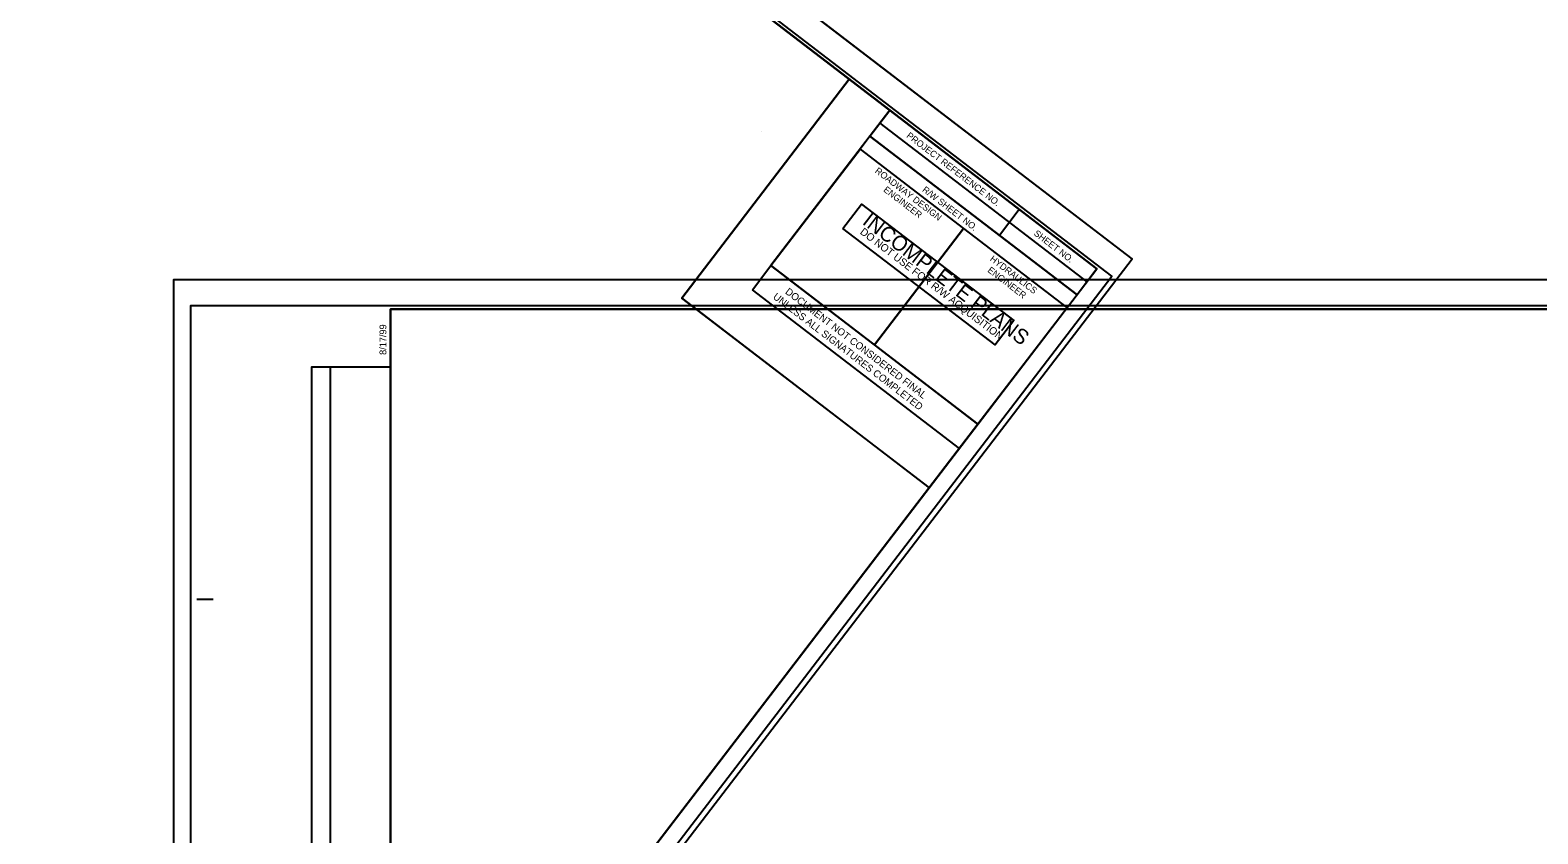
# Model space of a CAD drawing. Extents: x 1617779 to 1622406, y 896496 to 899510.
# Drawn here: x 1618935 to 1620092, y 898046 to 898662 of the extents above; entities that cross this region are included whole.
import ezdxf

# ---------------------------------------------------------------- set-up
doc = ezdxf.new("R2010")
doc.units = 0
for name, color, linetype in [('ControlPoints', 7, 'Continuous'), ('Exist Profile Cell', 7, 'Continuous'), ('Exist Vertical Profile Ground Line', 7, 'Continuous'), ('Exist Vertical Profile Horizontal Axis Label Major', 7, 'Continuous'), ('Observations', 7, 'Continuous'), ('Prop Horizontal Alignment', 7, 'Continuous'), ('Prop Horizontal Alignment Curve and Spiral Data', 7, 'Continuous'), ('Scratch_Level_4', 7, 'Continuous'), ('Setups', 7, 'Continuous')]:
    doc.layers.add(name, color=color, linetype=linetype)

msp = doc.modelspace()

# ---------------------------------------------------------------- linework, layer by layer
at = {"layer": 'ControlPoints'}
for points in [[(1617778.5, 898640.9), (1619115.1, 897617.3), (1619780.9, 898486.7), (1618444.3, 899510.3)], [(1619045.3, 897375.8), (1620728.8, 897375.8), (1620728.8, 898470.8), (1619045.3, 898470.8)]]:
    msp.add_lwpolyline(points, close=True, dxfattribs=at)
at = {"layer": 'Exist Profile Cell'}
for p, q in [((1619489.4, 898463), (1619503.7, 898481.6)), ((1619489.4, 898463), (1619503.7, 898481.6)), ((1619503.7, 898481.6), (1619662.5, 898360)), ((1619503.7, 898481.6), (1619662.5, 898360)), ((1619648.2, 898341.4), (1619489.4, 898463)), ((1619648.2, 898341.4), (1619489.4, 898463)), ((1619662.5, 898360), (1619648.2, 898341.4)), ((1619662.5, 898360), (1619648.2, 898341.4))]:
    msp.add_line(p, q, dxfattribs=at)
at = {"layer": 'Exist Vertical Profile Ground Line'}
msp.add_line((1619165.8, 897613.3), (1619165.8, 898403.9), dxfattribs=at)
msp.add_lwpolyline([(1619151.3, 897613.3), (1619151.3, 898403.9), (1619211.8, 898403.9), (1619211.8, 897613.3)], close=True, dxfattribs=at)
at = {"layer": 'Exist Vertical Profile Horizontal Axis Label Major'}
for p, q in [((1619587.3, 898590.8), (1619746.1, 898469.2)), ((1619579.6, 898580.9), (1619572.1, 898571)), ((1619579.6, 898580.9), (1619738.5, 898459.3)), ((1619579.6, 898580.9), (1619738.5, 898459.3)), ((1619694.1, 898524.7), (1619678.9, 898504.8)), ((1619651.5, 898510.1), (1619583.1, 898420.8)), ((1619211.8, 898448.3), (1619211.8, 898448.3)), ((1619063.3, 898225.8), (1619075.8, 898225.8))]:
    msp.add_line(p, q, dxfattribs=at)
for points in [[(1619753.7, 898479.1), (1618562.8, 899391.2), (1617924.4, 898557.6), (1619115.3, 897645.5)], [(1617924.4, 898557.6), (1618562.8, 899391.2), (1619594.9, 898600.8), (1619503.7, 898481.6), (1619662.5, 898360), (1619115.3, 897645.5)], [(1619594.9, 898600.8), (1619753.7, 898479.1), (1619738.5, 898459.3), (1619579.6, 898580.9)], [(1619572.1, 898571), (1619651.5, 898510.1), (1619583.1, 898420.8), (1619503.7, 898481.6)], [(1619651.5, 898510.1), (1619730.9, 898449.3), (1619662.5, 898360), (1619583.1, 898420.8)], [(1620711.8, 898448.3), (1619211.8, 898448.3), (1619211.8, 897398.3), (1620711.8, 897398.3)], [(1619211.8, 897398.3), (1619211.8, 898448.3), (1620511.7, 898448.3), (1620511.8, 898298.2), (1620711.8, 898298.2), (1620711.8, 897398.3)]]:
    msp.add_lwpolyline(points, close=True, dxfattribs=at)
at = {"layer": 'Observations'}
for points in [[(1618562.8, 899391.2), (1617924.4, 898557.6), (1619115.3, 897645.5), (1619625.1, 898311.3), (1619435.2, 898456.7), (1619563.8, 898624.6)], [(1619435.2, 898456.7), (1619625.1, 898311.2), (1619753.7, 898479.1), (1619563.8, 898624.6)], [(1619211.8, 898448.3), (1619211.8, 897398.3), (1620711.8, 897398.3), (1620711.8, 898236.8), (1620472.5, 898236.8), (1620472.5, 898448.3)]]:
    msp.add_lwpolyline(points, close=True, dxfattribs=at)
at = {"layer": 'Prop Horizontal Alignment'}
for p, q in [((1619780.9, 898486.7), (1618444.3, 899510.3)), ((1620728.8, 898470.8), (1619045.3, 898470.8)), ((1619045.3, 898470.8), (1619045.3, 897375.8))]:
    msp.add_line(p, q, dxfattribs=at)
at = {"layer": 'Prop Horizontal Alignment Curve and Spiral Data'}
msp.add_lwpolyline([(1619558.9, 898510.2), (1619573.2, 898528.8), (1619689.9, 898439.4), (1619675.6, 898420.8)], close=True, dxfattribs=at)
at = {"layer": 'Scratch_Level_4'}
msp.add_line((1619496.5, 898584.3), (1619496.5, 898584.3), dxfattribs=at)
at = {"layer": 'Setups'}
for points in [[(1617801, 898648.9), (1619123.7, 897636), (1619765.2, 898473.5), (1618442.5, 899486.5)], [(1619058.3, 897395.8), (1620724.3, 897395.8), (1620724.3, 898450.8), (1619058.3, 898450.8)]]:
    msp.add_lwpolyline(points, close=True, dxfattribs=at)

# ---------------------------------------------------------------- texts
at = {"layer": 'Exist Profile Cell'}
for s, p in [('UNLESS ALL SIGNATURES COMPLETED', (1619504.7, 898456.7)), ('UNLESS ALL SIGNATURES COMPLETED', (1619504.7, 898456.7)), ('DOCUMENT NOT CONSIDERED FINAL', (1619514.1, 898460.6)), ('DOCUMENT NOT CONSIDERED FINAL', (1619514.1, 898460.6))]:
    msp.add_text(s, height=5.5, rotation=322.554, dxfattribs=at).set_placement(p)
at = {"layer": 'Exist Vertical Profile Horizontal Axis Label Major'}
for s, height, rotation, p in [('PROJECT REFERENCE NO.', 5, 322.554, (1619607.2, 898580.4)), ('ROADWAY DESIGN', 5, 322.554, (1619583, 898553.4)), ('ENGINEER', 5, 322.554, (1619589.5, 898538.9)), ('R/W SHEET NO.', 5, 322.554, (1619619.3, 898538.9)), ('SHEET NO.', 5, 322.554, (1619704.9, 898505.4)), ('ENGINEER', 5, 322.554, (1619669.4, 898477.2)), ('HYDRAULICS', 5, 322.554, (1619671.2, 898485.8)), ('8/17/99', 5.25, 90, (1619208.6, 898413.1))]:
    msp.add_text(s, height=height, rotation=rotation, dxfattribs=at).set_placement(p)
at = {"layer": 'Prop Horizontal Alignment Curve and Spiral Data'}
for s, height, p in [('INCOMPLETE PLANS', 11.52, (1619573.1, 898514)), ('DO NOT USE FOR R/W ACQUISITION', 5.76, (1619571.5, 898506.5))]:
    msp.add_text(s, height=height, rotation=322.554, dxfattribs=at).set_placement(p)

doc.saveas('drawing.dxf')
